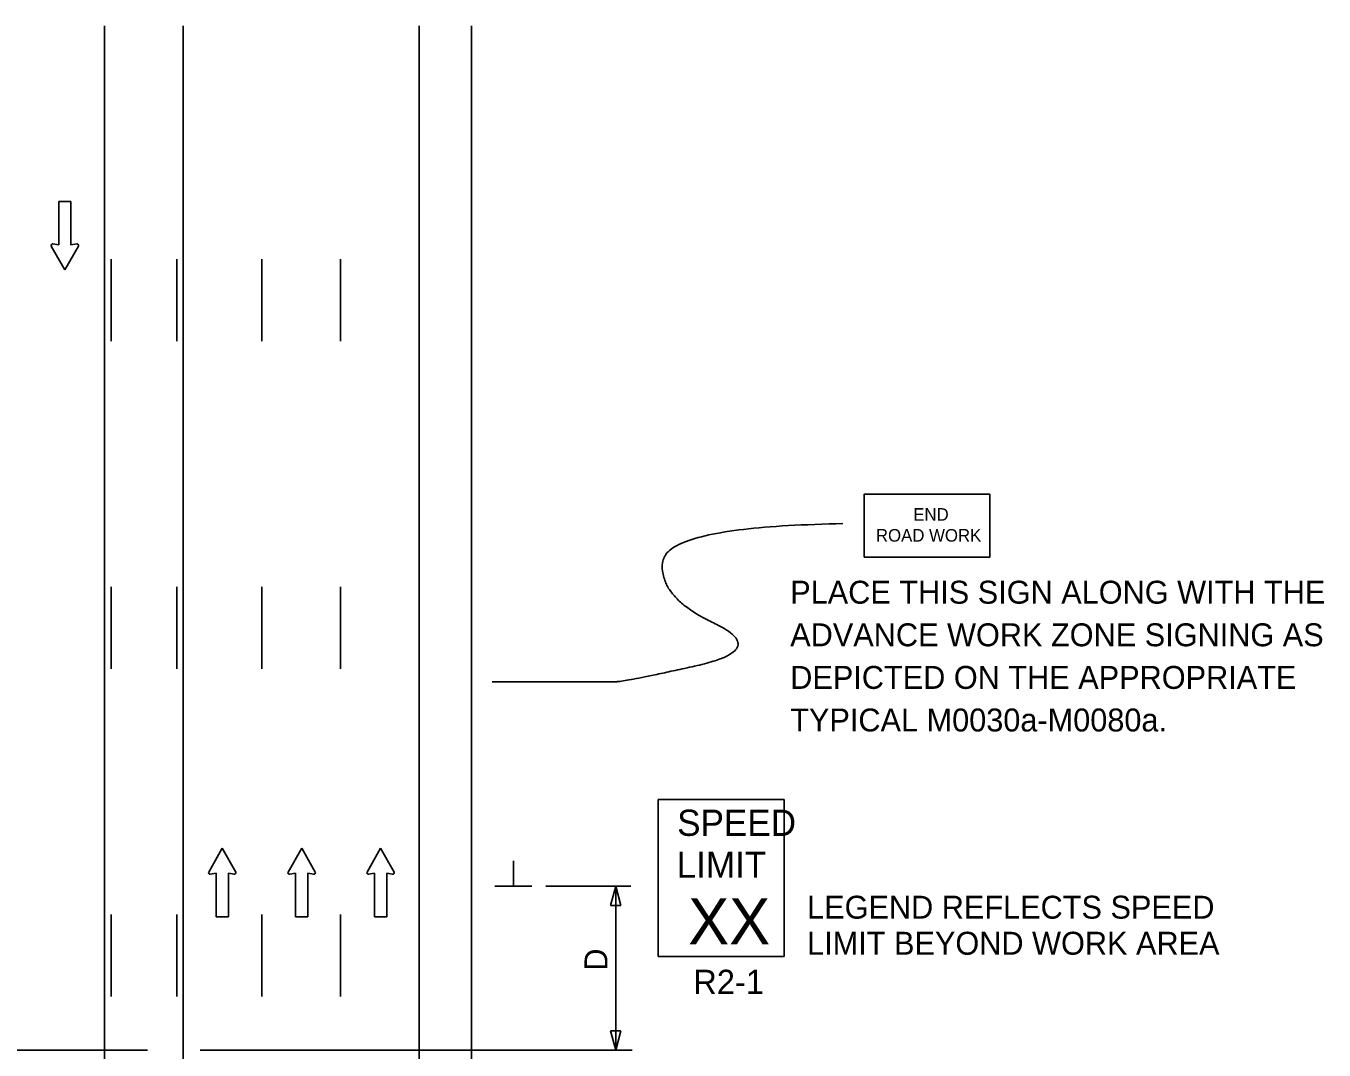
# Model space of a CAD drawing. Extents: x 16038 to 19504, y 5710 to 8321.
# Drawn here: x 17002.7 to 17398.9, y 6612.8 to 6925.3 of the extents above; entities that cross this region are included whole.
import ezdxf

# ---------------------------------------------------------------- set-up
doc = ezdxf.new("R2010")
doc.units = 0
for name, color, linetype in [('ALI_LEGAL_EX', 7, 'Continuous'), ('MT_SCRATCH_LEVEL_E', 7, 'Continuous'), ('PAVT_EDGE_EX', 7, 'Continuous'), ('TRAFFIC_SIGNS_PR', 7, 'Continuous'), ('TYPICAL_TEXT_DIMEN_PR', 7, 'Continuous')]:
    doc.layers.add(name, color=color, linetype=linetype)

msp = doc.modelspace()

# ---------------------------------------------------------------- linework, layer by layer
at = {"layer": 'ALI_LEGAL_EX'}
for points in [[(17028.71, 6829.12), (17028.71, 6854.12)], [(17048.71, 6829.12), (17048.71, 6854.12)], [(17074.71, 6829.12), (17074.71, 6854.12)], [(17098.71, 6829.12), (17098.71, 6854.12)], [(17028.71, 6729.12), (17028.71, 6754.12)], [(17048.71, 6729.12), (17048.71, 6754.12)], [(17074.71, 6729.12), (17074.71, 6754.12)], [(17098.71, 6729.12), (17098.71, 6754.12)], [(17028.71, 6629.12), (17028.71, 6654.12)], [(17048.71, 6629.12), (17048.71, 6654.12)], [(17074.71, 6629.12), (17074.71, 6654.12)], [(17098.71, 6629.12), (17098.71, 6654.12)]]:
    msp.add_lwpolyline(points, dxfattribs=at)
at = {"layer": 'MT_SCRATCH_LEVEL_E'}
for p, q in [((17016.45, 6871.76), (17012.71, 6871.76)), ((17012.71, 6871.76), (17012.71, 6858.5)), ((17016.45, 6871.76), (17012.71, 6871.76)), ((17012.71, 6871.76), (17012.71, 6858.5)), ((17016.45, 6858.5), (17016.45, 6871.76)), ((17016.45, 6858.5), (17016.45, 6871.76)), ((17010.45, 6858.13), (17014.6, 6850.89)), ((17010.45, 6858.13), (17014.6, 6850.89)), ((17012.71, 6858.5), (17010.93, 6858.82)), ((17012.71, 6858.5), (17010.93, 6858.82)), ((17014.6, 6850.89), (17018.71, 6858.13)), ((17014.6, 6850.89), (17018.71, 6858.13)), ((17018.23, 6858.82), (17016.45, 6858.5)), ((17018.23, 6858.82), (17016.45, 6858.5)), ((17062.58, 6674.37), (17058.47, 6667.13)), ((17062.58, 6674.37), (17058.47, 6667.13)), ((17066.73, 6667.13), (17062.58, 6674.37)), ((17066.73, 6667.13), (17062.58, 6674.37)), ((17086.85, 6674.37), (17082.74, 6667.13)), ((17086.85, 6674.37), (17082.74, 6667.13)), ((17090.99, 6667.13), (17086.85, 6674.37)), ((17090.99, 6667.13), (17086.85, 6674.37)), ((17110.92, 6674.37), (17106.81, 6667.13)), ((17110.92, 6674.37), (17106.81, 6667.13)), ((17115.07, 6667.13), (17110.92, 6674.37)), ((17115.07, 6667.13), (17110.92, 6674.37)), ((17058.95, 6666.44), (17060.73, 6666.76)), ((17058.95, 6666.44), (17060.73, 6666.76)), ((17060.73, 6666.76), (17060.73, 6653.5)), ((17060.73, 6666.76), (17060.73, 6653.5)), ((17064.47, 6653.5), (17064.47, 6666.76)), ((17064.47, 6666.76), (17066.25, 6666.44)), ((17064.47, 6653.5), (17064.47, 6666.76)), ((17064.47, 6666.76), (17066.25, 6666.44)), ((17083.22, 6666.44), (17085, 6666.76)), ((17083.22, 6666.44), (17085, 6666.76)), ((17085, 6666.76), (17085, 6653.5)), ((17085, 6666.76), (17085, 6653.5)), ((17088.74, 6653.5), (17088.74, 6666.76)), ((17088.74, 6666.76), (17090.52, 6666.44)), ((17088.74, 6653.5), (17088.74, 6666.76)), ((17088.74, 6666.76), (17090.52, 6666.44)), ((17107.29, 6666.44), (17109.07, 6666.76)), ((17107.29, 6666.44), (17109.07, 6666.76)), ((17109.07, 6666.76), (17109.07, 6653.5)), ((17109.07, 6666.76), (17109.07, 6653.5)), ((17112.81, 6653.5), (17112.81, 6666.76)), ((17112.81, 6666.76), (17114.59, 6666.44)), ((17112.81, 6653.5), (17112.81, 6666.76)), ((17112.81, 6666.76), (17114.59, 6666.44)), ((17060.73, 6653.5), (17064.47, 6653.5)), ((17060.73, 6653.5), (17064.47, 6653.5)), ((17085, 6653.5), (17088.74, 6653.5)), ((17085, 6653.5), (17088.74, 6653.5)), ((17109.07, 6653.5), (17112.81, 6653.5)), ((17109.07, 6653.5), (17112.81, 6653.5))]:
    msp.add_line(p, q, dxfattribs=at)
for centre, start, end in [((17010.86, 6858.36), 80.0362, 209.7731), ((17010.86, 6858.36), 80.0362, 209.7731), ((17018.3, 6858.36), 330.4248, 99.9638), ((17018.3, 6858.36), 330.4248, 99.9638), ((17058.88, 6666.9), 150.4248, 279.9638), ((17058.88, 6666.9), 150.4248, 279.9638), ((17066.32, 6666.9), 260.0362, 29.7731), ((17066.32, 6666.9), 260.0362, 29.7731), ((17083.14, 6666.9), 150.4248, 279.9638), ((17083.14, 6666.9), 150.4248, 279.9638), ((17090.59, 6666.9), 260.0362, 29.7731), ((17090.59, 6666.9), 260.0362, 29.7731), ((17107.22, 6666.9), 150.4248, 279.9638), ((17107.22, 6666.9), 150.4248, 279.9638), ((17114.66, 6666.9), 260.0362, 29.7731), ((17114.66, 6666.9), 260.0362, 29.7731)]:
    msp.add_arc(centre, 0.463, start, end, dxfattribs=at)
at = {"layer": 'PAVT_EDGE_EX'}
for p, q in [((17026.71, 6925.32), (17026.71, 6544.7)), ((17050.71, 6925.32), (17050.71, 6570.98)), ((17122.71, 6925.32), (17122.71, 6077.44)), ((17138.71, 6925.32), (17138.71, 6077.44)), ((17026.71, 6816.67), (17026.71, 6543.65)), ((17050.71, 6816.67), (17050.71, 6568.76))]:
    msp.add_line(p, q, dxfattribs=at)
at = {"layer": 'TRAFFIC_SIGNS_PR'}
for p, q in [((17195.68, 6689.3), (17234.08, 6689.3)), ((17195.68, 6641.3), (17195.68, 6689.3)), ((17234.08, 6641.3), (17234.08, 6689.3)), ((17195.68, 6641.3), (17234.08, 6641.3))]:
    msp.add_line(p, q, dxfattribs=at)
msp.add_lwpolyline([(17258.49, 6763.22), (17296.89, 6763.22), (17296.89, 6782.42), (17258.49, 6782.42)], close=True, dxfattribs=at)
at = {"layer": 'TYPICAL_TEXT_DIMEN_PR'}
for p, q in [((17151.47, 6662.8), (17151.47, 6670.59)), ((17157.09, 6662.8), (17145.84, 6662.8)), ((17161.34, 6662.8), (17187.34, 6662.8)), ((17181.14, 6656.94), (17182.71, 6662.8)), ((17182.71, 6662.8), (17182.71, 6612.8)), ((17182.71, 6662.8), (17184.28, 6656.94)), ((17182.71, 6656.94), (17181.14, 6656.94)), ((17184.28, 6656.94), (17182.71, 6656.94)), ((17182.71, 6612.8), (17181.14, 6618.67)), ((17181.14, 6618.67), (17182.71, 6618.67)), ((17182.71, 6618.67), (17184.28, 6618.67)), ((17184.28, 6618.67), (17182.71, 6612.8)), ((16889.61, 6612.8), (17039.81, 6612.8)), ((17187.71, 6612.8), (17055.85, 6612.8))]:
    msp.add_line(p, q, dxfattribs=at)
msp.add_open_spline([(17252.01, 6773.46), (17198.35, 6772.49), (17195.66, 6751.1), (17229.65, 6735.08), (17185.37, 6725.18), (17180.01, 6725.18), (17144.94, 6725.18)], degree=2, dxfattribs=at)

# ---------------------------------------------------------------- texts
at = {"layer": 'TRAFFIC_SIGNS_PR'}
for s, height, p in [('END', 3.831, (17273.49, 6774.35)), ('ROAD WORK', 3.831, (17262.1, 6767.96)), ('PLACE THIS SIGN ALONG WITH THE', 7, (17235.95, 6749.02)), ('ADVANCE WORK ZONE SIGNING AS', 7, (17235.95, 6736.02)), ('DEPICTED ON THE APPROPRIATE', 7, (17235.95, 6723.02)), ('TYPICAL M0030a-M0080a.', 7, (17235.95, 6710.02)), ('SPEED', 8, (17201.45, 6678.16)), ('LIMIT', 8, (17201.29, 6665.36)), ('XX', 14.031, (17204.8, 6645.06)), ('R2-1', 7.44, (17206.36, 6629.86))]:
    msp.add_text(s, height=height, dxfattribs=at).set_placement(p)
at = {"layer": 'TYPICAL_TEXT_DIMEN_PR'}
for s, p in [('LEGEND REFLECTS SPEED', (17241.1, 6652.89)), ('LIMIT BEYOND WORK AREA', (17241.1, 6641.89))]:
    msp.add_text(s, height=7, dxfattribs=at).set_placement(p)
msp.add_text('D', height=7, rotation=90, dxfattribs=at).set_placement((17180.15, 6637.02))

doc.saveas('drawing.dxf')
